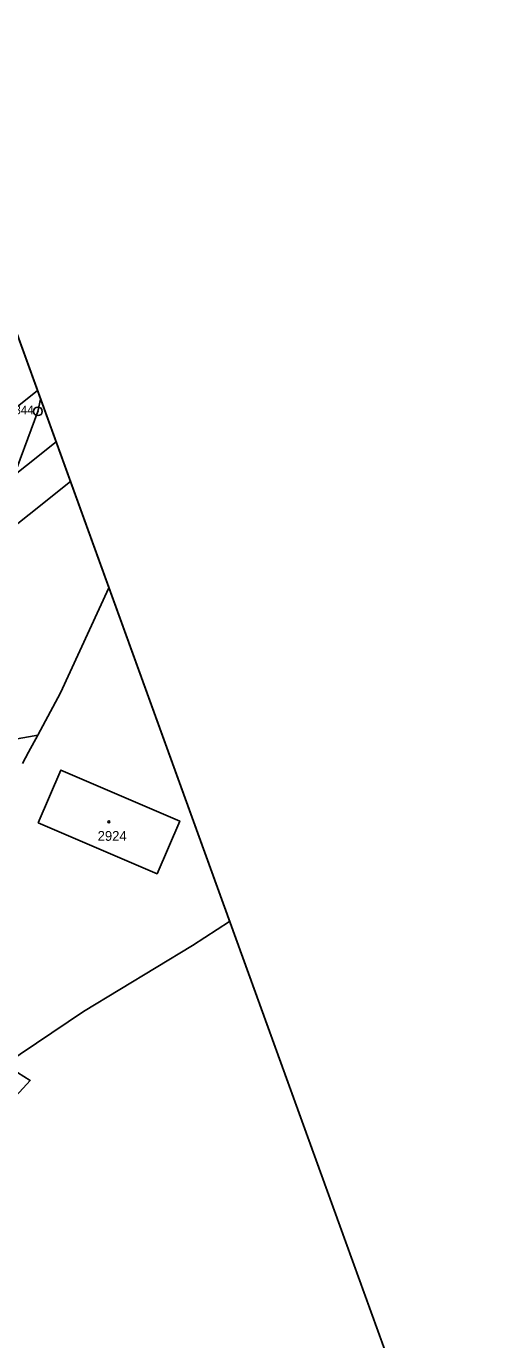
# Model space of a CAD drawing. Extents: x -620552 to -620056, y -1123312 to -1122890.
# Drawn here: x -620136.2 to -620056.1, y -1123118.1 to -1122889.6 of the extents above; entities that cross this region are included whole.
import ezdxf

# ---------------------------------------------------------------- set-up
doc = ezdxf.new("R2010")
doc.units = 0
for name, color, linetype in [('HranDP', 7, 'Continuous'), ('Hranice parcel', 7, 'Continuous'), ('Parcelní čísla', 7, 'Continuous'), ('Rámečky', 7, 'Continuous'), ('Rámečky-tisk', 7, 'Continuous'), ('Vrstva 33', 7, 'Continuous'), ('Značky bodu BP', 7, 'Continuous'), ('Značky budov', 7, 'Continuous')]:
    doc.layers.add(name, color=color, linetype=linetype)

msp = doc.modelspace()

# ---------------------------------------------------------------- linework, layer by layer
at = {"layer": 'HranDP'}
msp.add_lwpolyline([(-620139.01, -1122969.61), (-620134.15, -1122956.58), (-620133.7, -1122954.48)], dxfattribs=at)
at = {"layer": 'Hranice parcel'}
msp.add_line((-620138.43, -1123013.68), (-620134.2, -1123012.93), dxfattribs=at)
for points in [[(-620139.01, -1122969.61), (-620134.15, -1122956.58), (-620133.7, -1122954.48)], [(-620121.82, -1122987.28), (-620130.2, -1123005.56), (-620134.2, -1123012.93)], [(-620134.2, -1123012.93), (-620135.79, -1123015.87), (-620136.85, -1123017.81)], [(-620134.13, -1123028.15), (-620113.42, -1123037.02), (-620109.47, -1123027.84), (-620130.15, -1123018.97), (-620134.13, -1123028.15)], [(-620139.89, -1123070.16), (-620126.22, -1123060.97), (-620107.28, -1123049.5), (-620100.81, -1123045.29)], [(-620139.89, -1123070.16), (-620135.5, -1123072.99), (-620152.59, -1123091.6)]]:
    msp.add_lwpolyline(points, dxfattribs=at)
at = {"layer": 'Rámečky'}
msp.add_line((-620056.07, -1123168.86), (-620157.19, -1122889.6), dxfattribs=at)
at = {"layer": 'Rámečky-tisk'}
for points in [[(-620450.98, -1123311.85), (-620056.07, -1123168.86), (-620157.19, -1122889.6), (-620552.1, -1123032.6)], [(-620128.51, -1122968.81), (-620157.19, -1122889.6), (-620211.7, -1122909.34)], [(-620211.7, -1122909.34), (-620150.41, -1122986.26), (-620128.51, -1122968.81)]]:
    msp.add_lwpolyline(points, dxfattribs=at)
at = {"layer": 'Vrstva 33'}
for p, q in [((-620146.7, -1122962.91), (-620134.24, -1122952.98)), ((-620145.47, -1122973.44), (-620131.01, -1122961.91))]:
    msp.add_line(p, q, dxfattribs=at)
at = {"layer": 'Značky bodu BP'}
for radius in [0.75, 0.03]:
    msp.add_circle((-620134.15, -1122956.58), radius, dxfattribs=at)
at = {"layer": 'Značky budov'}
msp.add_circle((-620121.81, -1123027.99), 0.175, dxfattribs=at)

# ---------------------------------------------------------------- texts
at = {"layer": 'Parcelní čísla'}
msp.add_text('2924', height=1.7, dxfattribs=at).set_placement((-620123.77, -1123031.28))
at = {"layer": 'Značky bodu BP'}
msp.add_text('844', height=1.5, dxfattribs=at).set_placement((-620138.25, -1122957.08))

doc.saveas('drawing.dxf')
